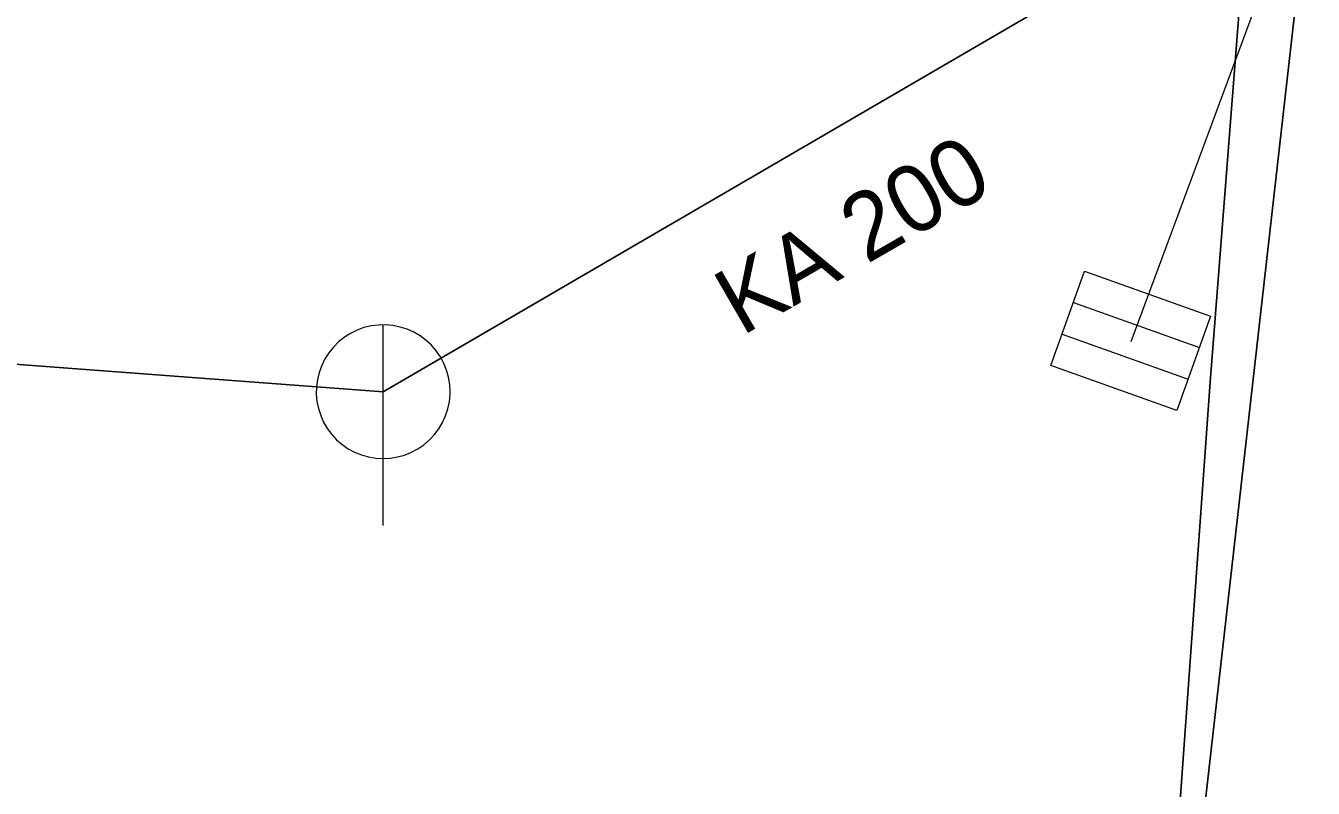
# Model space of a CAD drawing. Extents: x -783064 to -782702, y -1007904 to -1007145.
# Drawn here: x -782950.19 to -782930.95, y -1007414.46 to -1007403.06 of the extents above; entities that cross this region are included whole.
import ezdxf

# ---------------------------------------------------------------- set-up
doc = ezdxf.new("R2010")
doc.units = 0
doc.header["$LTSCALE"] = 0.4
for name, color, linetype, lineweight in [('1', 7, 'Continuous', 13), ('11', 7, 'Continuous', 13), ('14', 7, 'Continuous', 13), ('17', 7, 'Continuous', 25), ('22', 7, 'Continuous', 13)]:
    doc.layers.add(name, color=color, linetype=linetype, lineweight=lineweight)

msp = doc.modelspace()

# ---------------------------------------------------------------- linework, layer by layer
at = {"layer": '11'}
msp.add_line((-782933.669, -1007407.779), (-782930.949, -1007400.43), dxfattribs=at)
at = {"layer": '14', "lineweight": 25}
for p, q in [((-782944.85, -1007408.53), (-782930.949, -1007400.43)), ((-782939.739, -1007477.92), (-782930.949, -1007400.43)), ((-782963.94, -1007407.1), (-782944.85, -1007408.53))]:
    msp.add_line(p, q, dxfattribs=at)
at = {"layer": '17'}
msp.add_lwpolyline([(-782931.92, -1007401.104), (-782931.956, -1007401.549), (-782932.488, -1007408.389), (-782933.956, -1007428.826), (-782935.107, -1007441.291), (-782936.401, -1007452.394), (-782937.129, -1007459.088), (-782938.934, -1007480.861), (-782939.259, -1007494.042), (-782939.179, -1007503.419), (-782938.89, -1007514.33), (-782939.048, -1007525.032), (-782938.934, -1007539.638), (-782938.382, -1007552.936)], dxfattribs=at)
at = {"layer": '22'}
for p, q in [((-782934.534, -1007407.197), (-782932.651, -1007407.87)), ((-782944.85, -1007410.53), (-782944.849, -1007407.53)), ((-782934.702, -1007407.667), (-782932.819, -1007408.341))]:
    msp.add_line(p, q, dxfattribs=at)
for points in [[(-782934.366, -1007406.726), (-782932.483, -1007407.399), (-782932.988, -1007408.812), (-782934.871, -1007408.138)], [(-782943.85, -1007408.53), (-782943.855, -1007408.421), (-782943.873, -1007408.313), (-782943.903, -1007408.207), (-782943.943, -1007408.106), (-782943.995, -1007408.009), (-782944.057, -1007407.919), (-782944.129, -1007407.836), (-782944.209, -1007407.762), (-782944.297, -1007407.696), (-782944.391, -1007407.641), (-782944.491, -1007407.596), (-782944.596, -1007407.563), (-782944.703, -1007407.541), (-782944.812, -1007407.531), (-782944.922, -1007407.533), (-782945.03, -1007407.547), (-782945.137, -1007407.572), (-782945.24, -1007407.609), (-782945.338, -1007407.658), (-782945.43, -1007407.716), (-782945.516, -1007407.785), (-782945.593, -1007407.862), (-782945.662, -1007407.948), (-782945.721, -1007408.04), (-782945.769, -1007408.138), (-782945.806, -1007408.241), (-782945.832, -1007408.348), (-782945.846, -1007408.456), (-782945.849, -1007408.566), (-782945.839, -1007408.675), (-782945.818, -1007408.782), (-782945.784, -1007408.886), (-782945.74, -1007408.986), (-782945.685, -1007409.081), (-782945.619, -1007409.169), (-782945.545, -1007409.249), (-782945.462, -1007409.321), (-782945.372, -1007409.383), (-782945.276, -1007409.435), (-782945.174, -1007409.476), (-782945.069, -1007409.506), (-782944.961, -1007409.524), (-782944.851, -1007409.53), (-782944.742, -1007409.524), (-782944.634, -1007409.506), (-782944.529, -1007409.477), (-782944.427, -1007409.436), (-782944.33, -1007409.384), (-782944.24, -1007409.322), (-782944.157, -1007409.251), (-782944.082, -1007409.171), (-782944.017, -1007409.083), (-782943.961, -1007408.989), (-782943.917, -1007408.889), (-782943.883, -1007408.785), (-782943.861, -1007408.677), (-782943.851, -1007408.568)]]:
    msp.add_lwpolyline(points, close=True, dxfattribs=at)

# ---------------------------------------------------------------- texts
at = {"layer": '1'}
msp.add_text('KA 200', height=1, rotation=30, dxfattribs=at).set_placement((-782939.492, -1007407.705))

doc.saveas('drawing.dxf')
